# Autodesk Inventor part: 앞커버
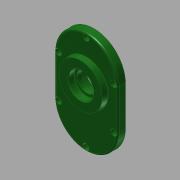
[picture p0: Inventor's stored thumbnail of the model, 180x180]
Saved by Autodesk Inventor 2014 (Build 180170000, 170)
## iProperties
Created: 2016-12
Part Number: 앞커버
Material: 일반
Document SubType Name: Modeling
Designer: mduedu
Density: 1 g/cm^3
Appearance: Smooth - Dark Forest Green
Mass: 97.7255 g
Surface Area: 264.104 cm^2
Volume: 97.7255 cm^3
Author: mduedu
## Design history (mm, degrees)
sketch "스케치1"
  geometry: L1 (40, -25)-(40, 25); L2 (-40, 25)-(-40, -25); L3 (-40, -25)-(40, 25); L4 (40, -25)-(-40, 25); A1 r 40 centre (0, 25) between (40, 25) and (-40, 25); A2 r 40 centre (0, -25) between (-40, -25) and (40, -25); 1 further point
  constraints: 8 end point, 4 point on circle, 4 tangent, 2 centre point, 2 midpoint, 1 parallel, 1 vertical
  dimensions: "d0" = 130 dimension on A2 A1; "d2" = 80 distance between parallel lines of L1 L2
extrude "돌출1" new body sketch "스케치1" distance "d3" = 10; taper "d4" = 0 deg
sketch "스케치2"
  geometry: C1 r 21 at (0, 11); 1 further point
  constraints: 1 centre point, 1 vertical alignment
  dimensions: "d5" = 42 diameter of C1; "d7" = 11 distance of C1.centre point (0, 0)
extrude "돌출2" join sketch "스케치2" distance "d8" = 7; taper "d9" = 0 deg
sketch "스케치3"
  geometry: C1 r 15 at (0, -33.1); C2 r 21 at (0, 11) reference; 1 further point
  constraints: 1 centre point, 1 vertical alignment
  dimensions: "d10" = 30 diameter of C1; "d71" = 44.1 distance of C1.centre C2.centre
extrude "돌출3" join sketch "스케치3" distance "d12" = 7; taper "d13" = 0 deg
sketch "스케치4"
  geometry: C1 r 28 at (0, 11); A1 r 21 centre (0, 11) between (8.978, -7.984) and (-8.978, -7.984) reference; 1 further point
  constraints: 1 centre point, 1 coincident
  dimensions: "d14" = 56 diameter of C1
extrude "돌출4" join sketch "스케치4" distance "d15" = 7; taper "d16" = -5 deg
hole "구멍1" diameter "d19" = 35; stored, may be unused: countersink angle "d23" = 90 deg, drill point angle "d25" = 0 deg; dims "d17" = 10, "d18" = 10, "d20" = 6, "d21" = 4, "d22" = 2, "d24" = 10
hole "구멍2" diameter "d28" = 22; stored, may be unused: countersink angle "d32" = 90 deg, drill point angle "d34" = 0 deg; dims "d26" = 10, "d27" = 10, "d29" = 6, "d30" = 4, "d31" = 2, "d33" = 7
hole "구멍3" diameter "d37" = 19; stored, may be unused: countersink angle "d41" = 90 deg, drill point angle "d43" = 0 deg; dims "d35" = 10, "d36" = 10, "d38" = 6, "d39" = 4, "d40" = 2, "d42" = 1
hole "구멍4" diameter "d46" = 32; stored, may be unused: countersink angle "d50" = 90 deg, drill point angle "d52" = 0 deg; dims "d44" = 10, "d45" = 10, "d47" = 6, "d48" = 4, "d49" = 2, "d51" = 8
hole "구멍5" diameter "d55" = 25; stored, may be unused: countersink angle "d59" = 90 deg, drill point angle "d61" = 0 deg; dims "d53" = 10, "d54" = 10, "d56" = 6, "d57" = 4, "d58" = 2, "d60" = 8
fillet "모깎기1" dims "d62" = 0.3
fillet "모깎기2" dims "d63" = 2
chamfer "모따기1" distance "d64" = 1; stored, may be unused: second distance "d65" = 2, angle "d66" = 45 deg
fillet "모깎기4" dims "d68" = 2
fillet "모깎기5" dims "d69" = 0.3
fillet "모깎기6" dims "d70" = 2
sketch "스케치5"
  geometry: L1 (-40, 25)-(-40, -25) reference; L2 (40, -25)-(40, 25) reference; L3 (35, 25)-(35, -25); L4 (-35, -25)-(-35, 25); A1 r 40 centre (0, 25) between (40, 25) and (-40, 25) reference; A2 r 40 centre (0, -25) between (-40, -25) and (40, -25) reference; A3 r 35 centre (0, 25) between (35, 25) and (-35, 25); A4 r 35 centre (0, -25) between (-35, -25) and (35, -25); 2 further points
  constraints: 5 point on circle, 4 end point, 2 centre point, 1 vertical alignment, 3 other
  dimensions: "d72" = 5 distance between parallel lines of L2 L3
sketch "스케치7"
  geometry: 1 further point
hole "구멍7" sketch "스케치7" at (0, 60) diameter "d80" = 4.5; stored, may be unused: countersink angle "d84" = 90 deg, drill point angle "d86" = 0 deg; dims "d81" = 6, "d82" = 8, "d83" = 4.6, "d85" = 8
node "솔리드1"
pattern_linear "직사각형 패턴1"
